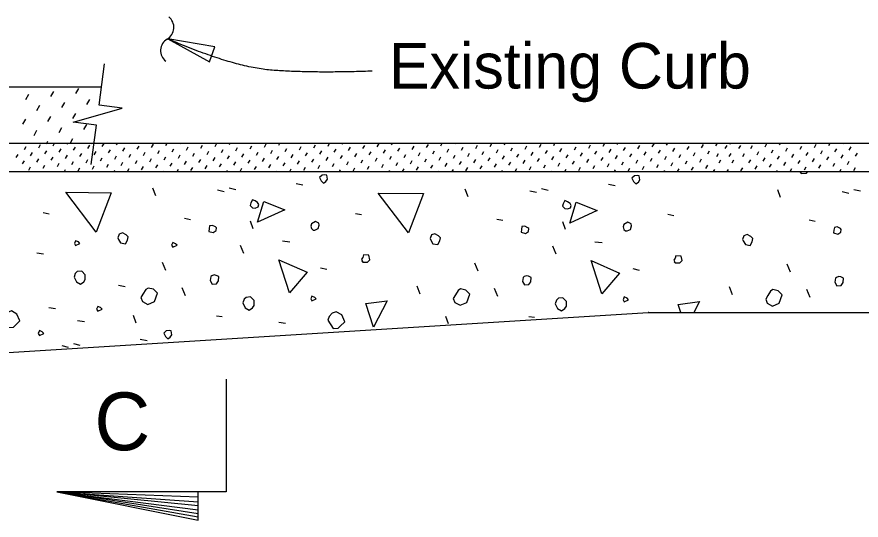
# Model space of a CAD drawing. Extents: x 1.5 to 68.7, y 0 to 31.1.
# Drawn here: x 6.295 to 10.034, y 9.315 to 11.544 of the extents above; entities that cross this region are included whole.
import ezdxf

# ---------------------------------------------------------------- set-up
doc = ezdxf.new("R2010")
doc.units = 0
for name, color, linetype in [('Dimension', 7, 'Continuous'), ('Miscellaneous', 7, 'Continuous'), ('TextStructures', 7, 'Continuous'), ('TrafBarrierConc', 7, 'Continuous')]:
    doc.layers.add(name, color=color, linetype=linetype)

msp = doc.modelspace()

# ---------------------------------------------------------------- linework, layer by layer
at = {"layer": 'Dimension'}
for p, q in [((7.0977, 9.4172), (6.4727, 9.4405)), ((6.4727, 9.4405), (7.0977, 9.3972)), ((7.0977, 9.3788), (6.4727, 9.4405)), ((6.4727, 9.4405), (7.0977, 9.3605)), ((7.0977, 9.3438), (6.4727, 9.4405)), ((6.4727, 9.4405), (7.0977, 9.3305))]:
    msp.add_line(p, q, dxfattribs=at)
msp.add_lwpolyline([(6.9637, 11.4471), (7.1488, 11.3454), (7.172, 11.412)], close=True, dxfattribs=at)
for points in [[(6.6242, 10.8911), (6.6474, 11.0649), (6.5449, 11.0786), (6.6533, 11.1095), (6.7617, 11.1405), (6.6593, 11.1541), (6.6836, 11.3365)], [(7.2227, 9.9405), (7.2227, 9.4405), (6.4727, 9.4405), (7.0977, 9.3155), (7.0977, 9.4405)]]:
    msp.add_lwpolyline(points, dxfattribs=at)
for centre, start, end in [((6.9312, 11.4974), 300.2724, 51.9996), ((6.9913, 11.3945), 120.2724, 231.9996)]:
    msp.add_arc(centre, 0.0596, start, end, dxfattribs=at)
msp.add_open_spline([(7.8694, 11.304), (7.5929, 11.2944), (7.2496, 11.323), (6.9636, 11.4471)], degree=2, dxfattribs=at)
at = {"layer": 'Miscellaneous'}
for p, q in [((6.5567, 11.2051), (6.5697, 11.2275)), ((6.3355, 11.1792), (6.3484, 11.2016)), ((6.4461, 11.1921), (6.4591, 11.2145)), ((6.3843, 11.1304), (6.3973, 11.1527)), ((6.4949, 11.1433), (6.5079, 11.1657)), ((6.6056, 11.1563), (6.6185, 11.1787)), ((6.5438, 11.0945), (6.5567, 11.1169)), ((6.3225, 11.0686), (6.3355, 11.0909)), ((6.4331, 11.0815), (6.4461, 11.1039)), ((6.5926, 11.0456), (6.6056, 11.068)), ((6.3713, 11.0197), (6.3843, 11.0421)), ((6.482, 11.0327), (6.4949, 11.0551)), ((6.4264, 10.9816), (6.4331, 10.9933)), ((6.5308, 10.9838), (6.5438, 11.0062)), ((6.3285, 10.9568), (6.3366, 10.9708)), ((6.392, 10.9649), (6.4001, 10.9789)), ((6.4555, 10.973), (6.4621, 10.9845)), ((6.4832, 10.9453), (6.4913, 10.9593)), ((6.519, 10.9811), (6.5209, 10.9845)), ((6.5467, 10.9534), (6.5548, 10.9674)), ((6.6102, 10.9616), (6.6183, 10.9755)), ((6.6274, 10.981), (6.6261, 10.9845)), ((6.6737, 10.9697), (6.6818, 10.9836)), ((6.7014, 10.942), (6.7095, 10.956)), ((6.7372, 10.9778), (6.7411, 10.9845)), ((6.7649, 10.9501), (6.773, 10.9641)), ((6.8283, 10.9582), (6.8364, 10.9722)), ((6.8918, 10.9663), (6.8999, 10.9803)), ((6.9553, 10.9744), (6.9612, 10.9845)), ((6.983, 10.9467), (6.9911, 10.9607)), ((7.0188, 10.9825), (7.02, 10.9845)), ((7.0465, 10.9548), (7.0546, 10.9688)), ((7.11, 10.9629), (7.1181, 10.9769)), ((7.1735, 10.971), (7.1813, 10.9845)), ((7.2012, 10.9433), (7.2093, 10.9573)), ((7.237, 10.9791), (7.2401, 10.9845)), ((7.2647, 10.9514), (7.2728, 10.9654)), ((7.3282, 10.9595), (7.3363, 10.9735)), ((7.3917, 10.9676), (7.3998, 10.9816)), ((7.4552, 10.9757), (7.4603, 10.9845)), ((7.4829, 10.948), (7.491, 10.962)), ((7.5187, 10.9838), (7.5191, 10.9845)), ((7.5464, 10.9561), (7.5545, 10.9701)), ((7.6098, 10.9642), (7.6179, 10.9782)), ((7.6733, 10.9723), (7.6804, 10.9845)), ((7.701, 10.9446), (7.7091, 10.9586)), ((7.7368, 10.9804), (7.7392, 10.9845)), ((7.7645, 10.9527), (7.7726, 10.9667)), ((7.828, 10.9608), (7.8361, 10.9748)), ((7.8915, 10.9689), (7.8996, 10.9829)), ((7.9192, 10.9412), (7.9273, 10.9552)), ((7.955, 10.977), (7.9593, 10.9845)), ((7.9827, 10.9493), (7.9908, 10.9633)), ((8.0462, 10.9574), (8.0543, 10.9714)), ((8.1097, 10.9655), (8.1178, 10.9795)), ((8.1732, 10.9736), (8.1795, 10.9845)), ((8.2009, 10.9459), (8.209, 10.9599)), ((8.2367, 10.9817), (8.2383, 10.9845)), ((8.2644, 10.954), (8.2725, 10.968)), ((8.3279, 10.9621), (8.336, 10.9761)), ((8.3913, 10.9702), (8.3994, 10.9842)), ((8.419, 10.9425), (8.4271, 10.9565)), ((8.4548, 10.9783), (8.4584, 10.9845)), ((8.4825, 10.9506), (8.4906, 10.9646)), ((8.546, 10.9588), (8.5541, 10.9727)), ((8.6095, 10.9669), (8.6176, 10.9808)), ((8.673, 10.975), (8.6785, 10.9845)), ((8.7007, 10.9473), (8.7088, 10.9613)), ((8.7365, 10.9831), (8.7373, 10.9845)), ((8.7642, 10.9554), (8.7723, 10.9694)), ((8.8277, 10.9635), (8.8358, 10.9775)), ((8.8912, 10.9716), (8.8987, 10.9845)), ((8.9189, 10.9439), (8.927, 10.9579)), ((8.9547, 10.9797), (8.9575, 10.9845)), ((8.9824, 10.952), (8.9905, 10.966)), ((9.0459, 10.9601), (9.054, 10.9741)), ((9.1094, 10.9682), (9.1175, 10.9822)), ((9.1728, 10.9763), (9.1776, 10.9845)), ((9.2005, 10.9486), (9.2086, 10.9626)), ((9.2363, 10.9844), (9.2364, 10.9845)), ((9.264, 10.9567), (9.2721, 10.9707)), ((9.3275, 10.9648), (9.3356, 10.9788)), ((9.391, 10.9729), (9.3977, 10.9845)), ((9.4322, 10.9614), (9.4403, 10.9754)), ((9.4545, 10.981), (9.4565, 10.9845)), ((9.4932, 10.9614), (9.5013, 10.9754)), ((9.5457, 10.9614), (9.5538, 10.9754)), ((9.6092, 10.9695), (9.6173, 10.9835)), ((9.6369, 10.9418), (9.645, 10.9558)), ((9.6727, 10.9776), (9.6767, 10.9845)), ((9.7004, 10.9499), (9.7085, 10.9639)), ((9.7639, 10.958), (9.772, 10.972)), ((9.8274, 10.9661), (9.8355, 10.9801)), ((9.8909, 10.9742), (9.8968, 10.9845)), ((9.9185, 10.9465), (9.9267, 10.9605)), ((9.9543, 10.9823), (9.9556, 10.9845)), ((9.982, 10.9546), (9.9901, 10.9686)), ((6.2927, 10.921), (6.3008, 10.935)), ((6.3562, 10.9291), (6.3643, 10.9431)), ((6.4197, 10.9372), (6.4278, 10.9512)), ((6.4474, 10.9095), (6.4555, 10.9235)), ((6.5109, 10.9177), (6.519, 10.9316)), ((6.5744, 10.9258), (6.5825, 10.9397)), ((6.6379, 10.9339), (6.646, 10.9479)), ((6.6656, 10.9062), (6.6737, 10.9202)), ((6.7291, 10.9143), (6.7372, 10.9283)), ((6.7925, 10.9224), (6.8006, 10.9364)), ((6.856, 10.9305), (6.8641, 10.9445)), ((6.9195, 10.9386), (6.9276, 10.9526)), ((6.9472, 10.9109), (6.9553, 10.9249)), ((7.0107, 10.919), (7.0188, 10.933)), ((7.0742, 10.9271), (7.0823, 10.9411)), ((7.1377, 10.9352), (7.1458, 10.9492)), ((7.1654, 10.9075), (7.1735, 10.9215)), ((7.2289, 10.9156), (7.237, 10.9296)), ((7.2924, 10.9237), (7.3005, 10.9377)), ((7.3559, 10.9318), (7.364, 10.9458)), ((7.3836, 10.9041), (7.3917, 10.9181)), ((7.4194, 10.9399), (7.4275, 10.9539)), ((7.4471, 10.9122), (7.4552, 10.9262)), ((7.5106, 10.9203), (7.5187, 10.9343)), ((7.574, 10.9284), (7.5821, 10.9424)), ((7.6375, 10.9365), (7.6456, 10.9505)), ((7.6652, 10.9088), (7.6733, 10.9228)), ((7.7287, 10.9169), (7.7368, 10.9309)), ((7.7922, 10.925), (7.8003, 10.939)), ((7.8557, 10.9331), (7.8638, 10.9471)), ((7.8834, 10.9054), (7.8915, 10.9194)), ((7.9469, 10.9135), (7.955, 10.9275)), ((8.0104, 10.9216), (8.0185, 10.9356)), ((8.0739, 10.9297), (8.082, 10.9437)), ((8.1374, 10.9378), (8.1455, 10.9518)), ((8.1651, 10.9101), (8.1732, 10.9241)), ((8.2286, 10.9182), (8.2367, 10.9322)), ((8.2921, 10.9263), (8.3002, 10.9403)), ((8.3555, 10.9344), (8.3636, 10.9484)), ((8.3832, 10.9067), (8.3913, 10.9207)), ((8.4467, 10.9149), (8.4548, 10.9288)), ((8.5102, 10.923), (8.5183, 10.9369)), ((8.5737, 10.9311), (8.5818, 10.9451)), ((8.6014, 10.9034), (8.6095, 10.9174)), ((8.6372, 10.9392), (8.6453, 10.9532)), ((8.6649, 10.9115), (8.673, 10.9255)), ((8.7284, 10.9196), (8.7365, 10.9336)), ((8.7919, 10.9277), (8.8, 10.9417)), ((8.8554, 10.9358), (8.8635, 10.9498)), ((8.8831, 10.9081), (8.8912, 10.9221)), ((8.9466, 10.9162), (8.9547, 10.9302)), ((9.0101, 10.9243), (9.0182, 10.9383)), ((9.0736, 10.9324), (9.0817, 10.9464)), ((9.1013, 10.9047), (9.1094, 10.9187)), ((9.137, 10.9405), (9.1451, 10.9545)), ((9.1647, 10.9128), (9.1728, 10.9268)), ((9.2282, 10.9209), (9.2363, 10.9349)), ((9.2917, 10.929), (9.2998, 10.943)), ((9.3552, 10.9371), (9.3633, 10.9511)), ((9.3948, 10.9256), (9.4029, 10.9396)), ((9.4506, 10.9256), (9.4587, 10.9396)), ((9.5099, 10.9256), (9.518, 10.9396)), ((9.5734, 10.9337), (9.5815, 10.9477)), ((9.6011, 10.906), (9.6092, 10.92)), ((9.6646, 10.9141), (9.6727, 10.9281)), ((9.7281, 10.9222), (9.7362, 10.9362)), ((9.7916, 10.9303), (9.7997, 10.9443)), ((9.8551, 10.9384), (9.8632, 10.9524)), ((9.8828, 10.9107), (9.8909, 10.9247)), ((9.9462, 10.9188), (9.9543, 10.9328)), ((10.0097, 10.9269), (10.0178, 10.9409)), ((6.3204, 10.8933), (6.3285, 10.9073)), ((6.3839, 10.9014), (6.392, 10.9154)), ((6.4116, 10.8738), (6.4197, 10.8877)), ((6.4751, 10.8819), (6.4832, 10.8958)), ((6.5386, 10.89), (6.5467, 10.904)), ((6.6021, 10.8981), (6.6102, 10.9121)), ((6.6298, 10.8704), (6.6379, 10.8844)), ((6.6933, 10.8785), (6.7014, 10.8925)), ((6.7567, 10.8866), (6.7649, 10.9006)), ((6.8202, 10.8947), (6.8283, 10.9087)), ((6.8479, 10.867), (6.856, 10.881)), ((6.8837, 10.9028), (6.8918, 10.9168)), ((6.9114, 10.8751), (6.9195, 10.8891)), ((6.9749, 10.8832), (6.983, 10.8972)), ((7.0384, 10.8913), (7.0465, 10.9053)), ((7.1019, 10.8994), (7.11, 10.9134)), ((7.1296, 10.8717), (7.1377, 10.8857)), ((7.1931, 10.8798), (7.2012, 10.8938)), ((7.2566, 10.8879), (7.2647, 10.9019)), ((7.3201, 10.896), (7.3282, 10.91)), ((7.3478, 10.8683), (7.3559, 10.8823)), ((7.4113, 10.8764), (7.4194, 10.8904)), ((7.4748, 10.8845), (7.4829, 10.8985)), ((7.5382, 10.8926), (7.5464, 10.9066)), ((7.6017, 10.9007), (7.6098, 10.9147)), ((7.6294, 10.873), (7.6375, 10.887)), ((7.6929, 10.8811), (7.701, 10.8951)), ((7.7564, 10.8892), (7.7645, 10.9032)), ((7.8199, 10.8973), (7.828, 10.9113)), ((7.8476, 10.8696), (7.8557, 10.8836)), ((7.9111, 10.8777), (7.9192, 10.8917)), ((7.9746, 10.8858), (7.9827, 10.8998)), ((8.0381, 10.8939), (8.0462, 10.9079)), ((8.0658, 10.8662), (8.0739, 10.8802)), ((8.1016, 10.902), (8.1097, 10.916)), ((8.1293, 10.8743), (8.1374, 10.8883)), ((8.1928, 10.8824), (8.2009, 10.8964)), ((8.2563, 10.8905), (8.2644, 10.9045)), ((8.3198, 10.8986), (8.3279, 10.9126)), ((8.3474, 10.871), (8.3555, 10.8849)), ((8.4109, 10.8791), (8.419, 10.893)), ((8.4744, 10.8872), (8.4825, 10.9012)), ((8.5379, 10.8953), (8.546, 10.9093)), ((8.5656, 10.8676), (8.5737, 10.8816)), ((8.6291, 10.8757), (8.6372, 10.8897)), ((8.6926, 10.8838), (8.7007, 10.8978)), ((8.7561, 10.8919), (8.7642, 10.9059)), ((8.8196, 10.9), (8.8277, 10.914)), ((8.8473, 10.8723), (8.8554, 10.8863)), ((8.9108, 10.8804), (8.9189, 10.8944)), ((8.9743, 10.8885), (8.9824, 10.9025)), ((9.0378, 10.8966), (9.0459, 10.9106)), ((9.0655, 10.8689), (9.0736, 10.8829)), ((9.1289, 10.877), (9.137, 10.891)), ((9.1924, 10.8851), (9.2005, 10.8991)), ((9.2559, 10.8932), (9.264, 10.9072)), ((9.3194, 10.9013), (9.3275, 10.9153)), ((9.3471, 10.8736), (9.3552, 10.8876)), ((9.4055, 10.8979), (9.4136, 10.9119)), ((9.4626, 10.8979), (9.4708, 10.9119)), ((9.5376, 10.8979), (9.5457, 10.9119)), ((9.5653, 10.8702), (9.5734, 10.8842)), ((9.6288, 10.8783), (9.6369, 10.8923)), ((9.6923, 10.8864), (9.7004, 10.9004)), ((9.7558, 10.8945), (9.7639, 10.9085)), ((9.7835, 10.8668), (9.7916, 10.8808)), ((9.8193, 10.9026), (9.8274, 10.9166)), ((9.847, 10.8749), (9.8551, 10.8889)), ((9.9104, 10.883), (9.9185, 10.897)), ((9.9739, 10.8911), (9.982, 10.9051)), ((6.3481, 10.8656), (6.3562, 10.8796)), ((6.4471, 10.8595), (6.4474, 10.8601)), ((6.5059, 10.8595), (6.5109, 10.8682)), ((6.5663, 10.8623), (6.5744, 10.8763)), ((6.726, 10.8595), (6.7291, 10.8648)), ((6.7848, 10.8595), (6.7925, 10.8729)), ((6.9461, 10.8595), (6.9472, 10.8614)), ((7.0049, 10.8595), (7.0107, 10.8695)), ((7.0661, 10.8636), (7.0742, 10.8776)), ((7.2251, 10.8595), (7.2289, 10.8661)), ((7.2843, 10.8602), (7.2924, 10.8742)), ((7.4452, 10.8595), (7.4471, 10.8627)), ((7.504, 10.8595), (7.5106, 10.8708)), ((7.5659, 10.8649), (7.574, 10.8789)), ((7.7241, 10.8595), (7.7287, 10.8674)), ((7.7841, 10.8615), (7.7922, 10.8755)), ((7.9443, 10.8595), (7.9469, 10.864)), ((8.0031, 10.8595), (8.0104, 10.8721)), ((8.1644, 10.8595), (8.1651, 10.8606)), ((8.2232, 10.8595), (8.2286, 10.8687)), ((8.284, 10.8629), (8.2921, 10.8768)), ((8.4433, 10.8595), (8.4467, 10.8654)), ((8.5021, 10.8595), (8.5102, 10.8735)), ((8.6635, 10.8595), (8.6649, 10.862)), ((8.7223, 10.8595), (8.7284, 10.8701)), ((8.7838, 10.8642), (8.7919, 10.8782)), ((8.9424, 10.8595), (8.9466, 10.8667)), ((9.002, 10.8608), (9.0101, 10.8748)), ((9.1625, 10.8595), (9.1647, 10.8633)), ((9.2213, 10.8595), (9.2282, 10.8714)), ((9.2836, 10.8655), (9.2917, 10.8795)), ((9.381, 10.8595), (9.386, 10.868)), ((9.3827, 10.8595), (9.3829, 10.8599)), ((9.4415, 10.8595), (9.4464, 10.868)), ((9.5018, 10.8621), (9.5099, 10.8761)), ((9.6616, 10.8595), (9.6646, 10.8646)), ((9.7204, 10.8595), (9.7281, 10.8727)), ((9.8817, 10.8595), (9.8828, 10.8612)), ((9.9405, 10.8595), (9.9462, 10.8693)), ((10.0016, 10.8634), (10.0097, 10.8774)), ((7.5318, 10.8065), (7.5619, 10.8012)), ((6.9105, 10.7517), (6.8981, 10.7852)), ((7.1845, 10.7782), (7.2128, 10.7711)), ((7.2362, 10.7875), (7.2645, 10.7804)), ((8.2938, 10.7481), (8.2814, 10.7817)), ((8.5678, 10.7746), (8.596, 10.7676)), ((8.6195, 10.7839), (8.6477, 10.7768)), ((8.9151, 10.8029), (8.9452, 10.7976)), ((9.677, 10.7446), (9.6647, 10.7782)), ((9.951, 10.7711), (9.9793, 10.764)), ((10.0027, 10.7804), (10.031, 10.7733)), ((6.412, 10.6774), (6.4385, 10.6721)), ((7.7952, 10.6739), (7.8218, 10.6686)), ((9.1785, 10.6703), (9.205, 10.665)), ((7.0378, 10.6527), (7.0643, 10.6474)), ((7.3423, 10.6063), (7.3299, 10.6398)), ((8.421, 10.6491), (8.4475, 10.6438)), ((8.7255, 10.6027), (8.7132, 10.6363)), ((9.8043, 10.6456), (9.8308, 10.6403)), ((7.4717, 10.5519), (7.5036, 10.5484)), ((8.855, 10.5484), (8.8868, 10.5448)), ((7.2998, 10.4967), (7.2857, 10.532)), ((8.6831, 10.4931), (8.669, 10.5285)), ((6.3839, 10.4998), (6.4139, 10.4945)), ((6.9547, 10.4211), (6.9405, 10.4564)), ((7.6397, 10.4335), (7.668, 10.4264)), ((8.3379, 10.4175), (8.3238, 10.4529)), ((9.7212, 10.414), (9.7071, 10.4494)), ((9.023, 10.4299), (9.0512, 10.4229)), ((6.7449, 10.3562), (6.7749, 10.3509)), ((7.0417, 10.3093), (7.0276, 10.3446)), ((8.0816, 10.3168), (8.0675, 10.3521)), ((8.425, 10.3057), (8.4109, 10.3411)), ((9.4649, 10.3132), (9.4508, 10.3486)), ((9.8083, 10.3022), (9.7941, 10.3376)), ((6.4372, 10.2577), (6.4672, 10.2524)), ((6.8239, 10.1877), (6.8115, 10.2213)), ((7.1796, 10.2209), (7.2044, 10.2173)), ((8.2071, 10.1842), (8.1948, 10.2178)), ((8.5629, 10.2173), (8.5876, 10.2138)), ((6.5644, 10.2002), (6.5944, 10.1949)), ((7.4554, 10.1926), (7.4854, 10.1873)), ((6.5463, 10.0976), (6.5746, 10.0905)), ((6.842, 10.1166), (6.872, 10.1113)), ((6.4946, 10.0883), (6.5229, 10.0812))]:
    msp.add_line(p, q, dxfattribs=at)
for points in [[(7.6432, 10.8188), (7.6538, 10.8082), (7.6644, 10.8153), (7.6715, 10.8259), (7.668, 10.8436), (7.6591, 10.8453), (7.6467, 10.8436), (7.6361, 10.833), (7.6432, 10.8188)], [(9.7635, 10.8594), (9.769, 10.8507), (9.7919, 10.8524), (9.7989, 10.8594)], [(9.0265, 10.8153), (9.0371, 10.8047), (9.0477, 10.8118), (9.0548, 10.8224), (9.0512, 10.84), (9.0424, 10.8418), (9.03, 10.84), (9.0194, 10.8294), (9.0265, 10.8153)], [(6.6471, 10.5908), (6.5127, 10.7676), (6.7125, 10.7658), (6.6471, 10.5908)], [(7.3387, 10.6991), (7.3511, 10.6973), (7.3635, 10.7026), (7.367, 10.7132), (7.3617, 10.722), (7.3511, 10.7291), (7.3387, 10.7344), (7.3316, 10.7203), (7.3281, 10.7097), (7.3387, 10.6991)], [(8.0304, 10.5873), (7.896, 10.764), (8.0958, 10.7623), (8.0304, 10.5873)], [(8.722, 10.6955), (8.7344, 10.6938), (8.7467, 10.6991), (8.7503, 10.7097), (8.745, 10.7185), (8.7344, 10.7256), (8.722, 10.7309), (8.7149, 10.7167), (8.7114, 10.7061), (8.722, 10.6955)], [(7.3604, 10.635), (7.3887, 10.7269), (7.4823, 10.6898), (7.3604, 10.635)], [(8.7436, 10.6314), (8.7719, 10.7234), (8.8656, 10.6862), (8.7436, 10.6314)], [(7.1456, 10.5943), (7.165, 10.589), (7.1774, 10.5979), (7.1792, 10.6102), (7.1756, 10.6138), (7.1615, 10.6208), (7.1491, 10.6191), (7.1474, 10.6067), (7.1456, 10.5943)], [(7.6079, 10.5996), (7.6149, 10.5996), (7.6291, 10.6067), (7.6344, 10.6226), (7.6326, 10.6314), (7.6185, 10.6385), (7.6008, 10.6279), (7.5973, 10.6173), (7.6008, 10.6067), (7.6079, 10.5996)], [(8.9911, 10.5961), (8.9982, 10.5961), (9.0123, 10.6032), (9.0177, 10.6191), (9.0159, 10.6279), (9.0017, 10.635), (8.9841, 10.6244), (8.9805, 10.6138), (8.9841, 10.6032), (8.9911, 10.5961)], [(6.7461, 10.559), (6.7549, 10.5431), (6.7761, 10.5395), (6.785, 10.5554), (6.7885, 10.5696), (6.7797, 10.5784), (6.7637, 10.5873), (6.7478, 10.582), (6.7425, 10.566), (6.7461, 10.559)], [(8.1293, 10.5554), (8.1382, 10.5395), (8.1594, 10.536), (8.1682, 10.5519), (8.1718, 10.566), (8.1629, 10.5749), (8.147, 10.5837), (8.1311, 10.5784), (8.1258, 10.5625), (8.1293, 10.5554)], [(8.5289, 10.5908), (8.5483, 10.5855), (8.5607, 10.5943), (8.5625, 10.6067), (8.5589, 10.6102), (8.5448, 10.6173), (8.5324, 10.6155), (8.5306, 10.6032), (8.5289, 10.5908)], [(9.9121, 10.5873), (9.9316, 10.582), (9.944, 10.5908), (9.9457, 10.6032), (9.9422, 10.6067), (9.9281, 10.6138), (9.9157, 10.612), (9.9139, 10.5996), (9.9121, 10.5873)], [(6.5552, 10.532), (6.5747, 10.5408), (6.5676, 10.5479), (6.5552, 10.5532), (6.5499, 10.5408), (6.5552, 10.532)], [(6.9859, 10.5238), (7.0054, 10.5326), (6.9983, 10.5397), (6.9859, 10.545), (6.9806, 10.5326), (6.9859, 10.5238)], [(9.5126, 10.5519), (9.5215, 10.536), (9.5427, 10.5325), (9.5515, 10.5484), (9.5551, 10.5625), (9.5462, 10.5713), (9.5303, 10.5802), (9.5144, 10.5749), (9.5091, 10.559), (9.5126, 10.5519)], [(7.8271, 10.4582), (7.8483, 10.4582), (7.8589, 10.4688), (7.8536, 10.4883), (7.8306, 10.49), (7.8271, 10.4794), (7.8218, 10.4706), (7.8271, 10.4582), (7.8235, 10.4617)], [(9.2103, 10.4547), (9.2316, 10.4547), (9.2422, 10.4653), (9.2369, 10.4847), (9.2139, 10.4865), (9.2103, 10.4759), (9.205, 10.467), (9.2103, 10.4547), (9.2068, 10.4582)], [(7.5031, 10.3216), (7.4554, 10.4684), (7.5809, 10.4136), (7.5031, 10.3216)], [(8.8864, 10.3181), (8.8387, 10.4648), (8.9642, 10.41), (8.8864, 10.3181)], [(6.5488, 10.3918), (6.5594, 10.3706), (6.5771, 10.36), (6.5913, 10.3706), (6.5983, 10.3812), (6.5983, 10.4024), (6.5824, 10.4183), (6.563, 10.4165), (6.5541, 10.4077), (6.5488, 10.3918)], [(7.1513, 10.3764), (7.1602, 10.3605), (7.1796, 10.3623), (7.1885, 10.3747), (7.1902, 10.3941), (7.1778, 10.3994), (7.169, 10.4012), (7.1584, 10.3977), (7.1549, 10.3941), (7.1513, 10.3764)], [(8.5346, 10.3729), (8.5434, 10.357), (8.5629, 10.3588), (8.5717, 10.3711), (8.5735, 10.3906), (8.5611, 10.3959), (8.5523, 10.3977), (8.5417, 10.3941), (8.5381, 10.3906), (8.5346, 10.3729)], [(9.9179, 10.3694), (9.9267, 10.3535), (9.9462, 10.3552), (9.955, 10.3676), (9.9568, 10.3871), (9.9444, 10.3924), (9.9356, 10.3941), (9.925, 10.3906), (9.9214, 10.3871), (9.9179, 10.3694)], [(6.8521, 10.2832), (6.8751, 10.2708), (6.9052, 10.2832), (6.9175, 10.3203), (6.8999, 10.338), (6.8769, 10.3433), (6.8663, 10.3362), (6.8539, 10.3168), (6.8451, 10.3009), (6.8521, 10.2832)], [(8.2354, 10.2797), (8.2584, 10.2673), (8.2884, 10.2797), (8.3008, 10.3168), (8.2831, 10.3345), (8.2602, 10.3398), (8.2496, 10.3327), (8.2372, 10.3132), (8.2283, 10.2973), (8.2354, 10.2797)], [(9.6187, 10.2761), (9.6417, 10.2638), (9.6717, 10.2761), (9.6841, 10.3132), (9.6664, 10.3309), (9.6434, 10.3362), (9.6328, 10.3292), (9.6205, 10.3097), (9.6116, 10.2938), (9.6187, 10.2761)], [(7.2963, 10.2775), (7.3069, 10.2562), (7.3246, 10.2456), (7.3387, 10.2562), (7.3458, 10.2668), (7.3458, 10.2881), (7.3299, 10.304), (7.3104, 10.3022), (7.3016, 10.2934), (7.2963, 10.2775)], [(7.6021, 10.2863), (7.6216, 10.2951), (7.6145, 10.3022), (7.6021, 10.3075), (7.5968, 10.2951), (7.6021, 10.2863)], [(7.8748, 10.1701), (7.8412, 10.2744), (7.9349, 10.2867), (7.8748, 10.1701)], [(8.6796, 10.2739), (8.6902, 10.2527), (8.7079, 10.2421), (8.722, 10.2527), (8.7291, 10.2633), (8.7291, 10.2845), (8.7132, 10.3004), (8.6937, 10.2987), (8.6849, 10.2898), (8.6796, 10.2739)], [(8.9854, 10.2828), (9.0048, 10.2916), (8.9978, 10.2987), (8.9854, 10.304), (8.9801, 10.2916), (8.9854, 10.2828)], [(9.2362, 10.2344), (9.2245, 10.2708), (9.3182, 10.2832), (9.2931, 10.2344)], [(6.6537, 10.2406), (6.6731, 10.2494), (6.666, 10.2565), (6.6537, 10.2618), (6.6484, 10.2494), (6.6537, 10.2406)], [(6.2339, 10.205), (6.2568, 10.1679), (6.2798, 10.1696), (6.2887, 10.1785), (6.3081, 10.1979), (6.2957, 10.228), (6.271, 10.2421), (6.2533, 10.235), (6.2392, 10.2209), (6.2339, 10.205)], [(7.6728, 10.2014), (7.6958, 10.1643), (7.7188, 10.1661), (7.7276, 10.1749), (7.7471, 10.1944), (7.7347, 10.2244), (7.7099, 10.2386), (7.6923, 10.2315), (7.6781, 10.2173), (7.6728, 10.2014)], [(9.0942, 10.2344), (9.0932, 10.235), (9.0918, 10.2344)], [(6.3952, 10.1339), (6.4147, 10.1427), (6.4076, 10.1498), (6.3952, 10.1551), (6.3899, 10.1427), (6.3952, 10.1339)], [(6.9533, 10.129), (6.9639, 10.1184), (6.9746, 10.1254), (6.9816, 10.136), (6.9781, 10.1537), (6.9693, 10.1555), (6.9569, 10.1537), (6.9463, 10.1431), (6.9533, 10.129)]]:
    msp.add_lwpolyline(points, dxfattribs=at)
at = {"layer": 'TrafBarrierConc'}
for p, q in [((4.4082, 11.2345), (6.67, 11.2345)), ((3.8717, 10.9845), (18.1441, 10.9845)), ((5.8718, 10.8595), (11.8162, 10.8595)), ((5.0917, 9.9844), (9.0917, 10.2344)), ((9.0917, 10.2345), (18.1442, 10.2345))]:
    msp.add_line(p, q, dxfattribs=at)

# ---------------------------------------------------------------- texts
at = {"layer": 'TextStructures'}
for s, height, p in [('Existing Curb', 0.2016, (7.9428, 11.227)), ('C', 0.256, (6.6388, 9.6249))]:
    msp.add_text(s, height=height, dxfattribs=at).set_placement(p)

doc.saveas('drawing.dxf')
